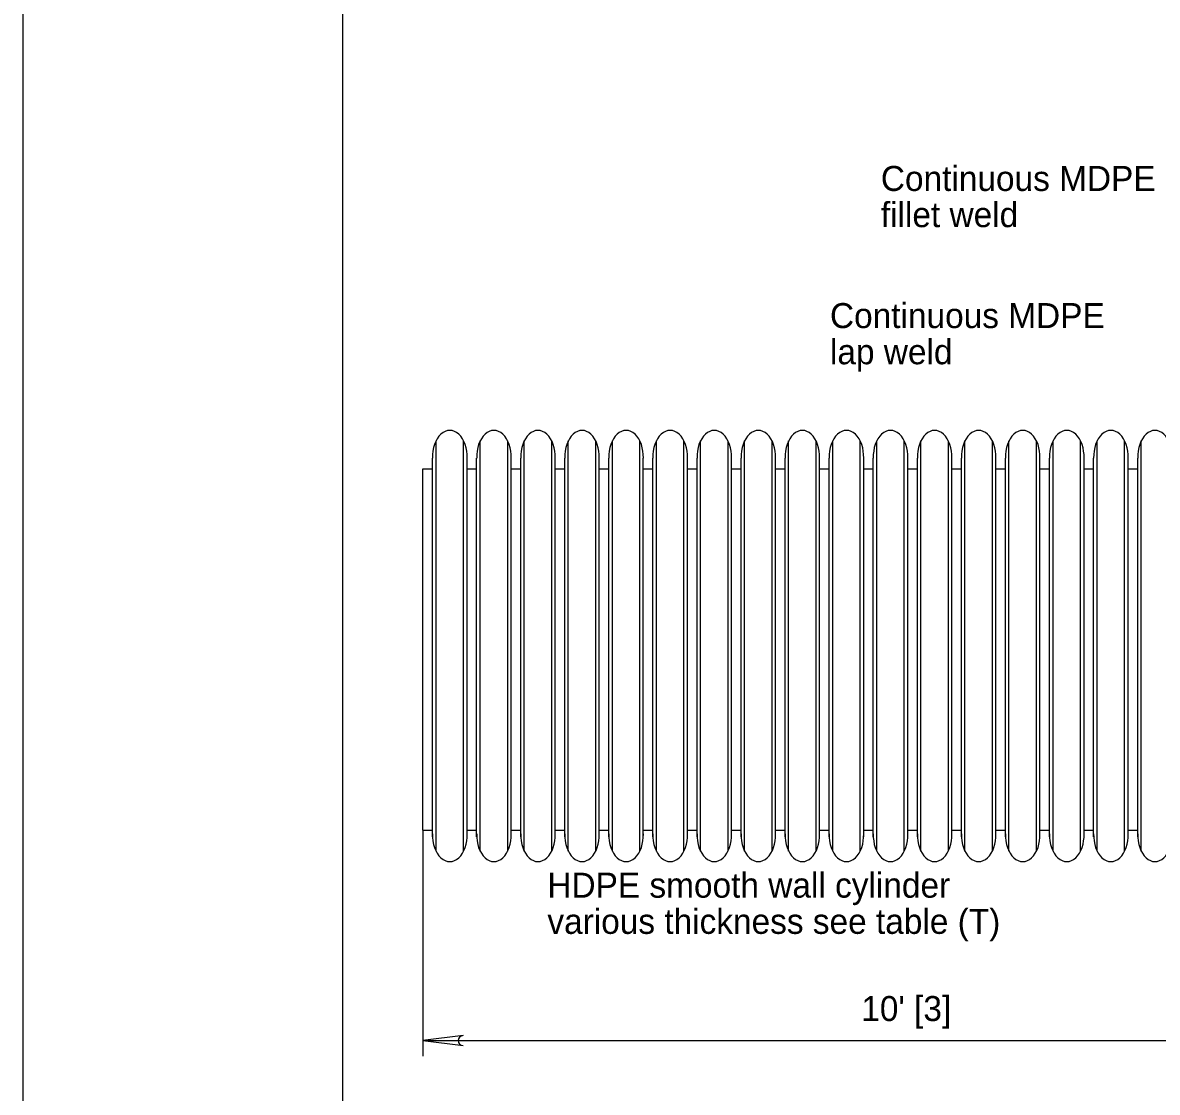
# Model space of a CAD drawing. Extents: x 1083.1 to 1117.1, y 675.4 to 741.4.
# Drawn here: x 1083.13 to 1090.21, y 684.37 to 691.05 of the extents above; entities that cross this region are included whole.
import ezdxf

# ---------------------------------------------------------------- set-up
doc = ezdxf.new("R2010")
doc.units = 0
doc.layers.add('Level 1', color=7, linetype='Continuous')
doc.layers.add('Level 44', color=7, linetype='Continuous')

msp = doc.modelspace()

# ---------------------------------------------------------------- linework, layer by layer
at = {"layer": 'Level 1'}
for p, q in [((1083.1264, 697.3541), (1083.1264, 675.3541)), ((1085.7082, 685.8738), (1085.7082, 688.4351)), ((1085.8803, 685.8738), (1085.8803, 688.4351)), ((1085.9834, 685.8738), (1085.9834, 688.4351)), ((1086.1556, 685.8738), (1086.1556, 688.4351)), ((1086.2587, 685.8738), (1086.2587, 688.4351)), ((1086.4308, 685.8738), (1086.4308, 688.4351)), ((1086.5339, 685.8738), (1086.5339, 688.4351)), ((1086.7061, 685.8738), (1086.7061, 688.4351)), ((1086.8092, 685.8738), (1086.8092, 688.4351)), ((1086.9813, 685.8738), (1086.9813, 688.4351)), ((1087.0844, 685.8738), (1087.0844, 688.4351)), ((1087.2566, 685.8738), (1087.2566, 688.4351)), ((1087.3597, 685.8738), (1087.3597, 688.4351)), ((1087.5318, 685.8738), (1087.5318, 688.4351)), ((1087.6349, 685.8738), (1087.6349, 688.4351)), ((1087.8071, 685.8738), (1087.8071, 688.4351)), ((1087.9102, 685.8738), (1087.9102, 688.4351)), ((1088.0823, 685.8738), (1088.0823, 688.4351)), ((1088.1854, 685.8738), (1088.1854, 688.4351)), ((1088.3576, 685.8738), (1088.3576, 688.4351)), ((1088.4607, 685.8738), (1088.4607, 688.4351)), ((1088.6328, 685.8738), (1088.6328, 688.4351)), ((1088.7359, 685.8738), (1088.7359, 688.4351)), ((1088.9081, 685.8738), (1088.9081, 688.4351)), ((1089.0112, 685.8738), (1089.0112, 688.4351)), ((1089.1833, 685.8738), (1089.1833, 688.4351)), ((1089.2864, 685.8738), (1089.2864, 688.4351)), ((1089.4586, 685.8738), (1089.4586, 688.4351)), ((1089.5617, 685.8738), (1089.5617, 688.4351)), ((1089.7338, 685.8738), (1089.7338, 688.4351)), ((1089.8369, 685.8738), (1089.8369, 688.4351)), ((1090.0091, 685.8738), (1090.0091, 688.4351)), ((1090.1122, 685.8738), (1090.1122, 688.4351)), ((1085.6865, 685.9635), (1085.6865, 688.3271)), ((1085.9018, 685.9633), (1085.9018, 688.3271)), ((1085.9617, 685.9635), (1085.9617, 688.3271)), ((1086.1771, 685.9633), (1086.1771, 688.3271)), ((1086.237, 685.9635), (1086.237, 688.3271)), ((1086.4523, 685.9633), (1086.4523, 688.3271)), ((1086.5122, 685.9635), (1086.5122, 688.3271)), ((1086.7276, 685.9633), (1086.7276, 688.3271)), ((1086.7875, 685.9635), (1086.7875, 688.3271)), ((1087.0028, 685.9633), (1087.0028, 688.3271)), ((1087.0628, 685.9635), (1087.0628, 688.3271)), ((1087.2781, 685.9633), (1087.2781, 688.3271)), ((1087.338, 685.9635), (1087.338, 688.3271)), ((1087.5533, 685.9633), (1087.5533, 688.3271)), ((1087.6132, 685.9635), (1087.6132, 688.3271)), ((1087.8286, 685.9633), (1087.8286, 688.3271)), ((1087.8885, 685.9635), (1087.8885, 688.3271)), ((1088.1038, 685.9633), (1088.1038, 688.3271)), ((1088.1637, 685.9635), (1088.1637, 688.3271)), ((1088.3791, 685.9633), (1088.3791, 688.3271)), ((1088.439, 685.9635), (1088.439, 688.3271)), ((1088.6543, 685.9633), (1088.6543, 688.3271)), ((1088.7142, 685.9635), (1088.7142, 688.3271)), ((1088.9296, 685.9633), (1088.9296, 688.3271)), ((1088.9895, 685.9635), (1088.9895, 688.3271)), ((1089.2048, 685.9633), (1089.2048, 688.3271)), ((1089.2648, 685.9635), (1089.2648, 688.3271)), ((1089.4801, 685.9633), (1089.4801, 688.3271)), ((1089.54, 685.9635), (1089.54, 688.3271)), ((1089.7553, 685.9633), (1089.7553, 688.3271)), ((1089.8152, 685.9635), (1089.8152, 688.3271)), ((1090.0306, 685.9633), (1090.0306, 688.3271)), ((1090.0905, 685.9635), (1090.0905, 688.3271)), ((1085.6266, 686.0051), (1085.6266, 688.2614)), ((1085.6266, 688.2614), (1085.6865, 688.2614)), ((1085.9018, 688.2614), (1085.9617, 688.2614)), ((1086.1771, 688.2614), (1086.237, 688.2614)), ((1086.4523, 688.2614), (1086.5122, 688.2614)), ((1086.7276, 688.2614), (1086.7875, 688.2614)), ((1087.0028, 688.2614), (1087.0628, 688.2614)), ((1087.2781, 688.2614), (1087.338, 688.2614)), ((1087.5533, 688.2614), (1087.6132, 688.2614)), ((1087.8286, 688.2614), (1087.8885, 688.2614)), ((1088.1038, 688.2614), (1088.1637, 688.2614)), ((1088.3791, 688.2614), (1088.439, 688.2614)), ((1088.6543, 688.2614), (1088.7142, 688.2614)), ((1088.9296, 688.2614), (1088.9895, 688.2614)), ((1089.2048, 688.2614), (1089.2648, 688.2614)), ((1089.4801, 688.2614), (1089.54, 688.2614)), ((1089.7553, 688.2614), (1089.8152, 688.2614)), ((1090.0306, 688.2614), (1090.0905, 688.2614)), ((1085.6266, 686.0051), (1085.6865, 686.0051)), ((1085.6266, 686.0051), (1085.6266, 684.5927)), ((1085.9018, 686.0051), (1085.9617, 686.0051)), ((1086.1771, 686.0051), (1086.237, 686.0051)), ((1086.4523, 686.0051), (1086.5122, 686.0051)), ((1086.7276, 686.0051), (1086.7875, 686.0051)), ((1087.0028, 686.0051), (1087.0628, 686.0051)), ((1087.2781, 686.0051), (1087.338, 686.0051)), ((1087.5533, 686.0051), (1087.6132, 686.0051)), ((1087.8286, 686.0051), (1087.8885, 686.0051)), ((1088.1038, 686.0051), (1088.1637, 686.0051)), ((1088.3791, 686.0051), (1088.439, 686.0051)), ((1088.6543, 686.0051), (1088.7142, 686.0051)), ((1088.9296, 686.0051), (1088.9895, 686.0051)), ((1089.2048, 686.0051), (1089.2648, 686.0051)), ((1089.4801, 686.0051), (1089.54, 686.0051)), ((1089.7553, 686.0051), (1089.8152, 686.0051)), ((1090.0306, 686.0051), (1090.0905, 686.0051)), ((1085.6266, 684.6905), (1092.023, 684.6905))]:
    msp.add_line(p, q, dxfattribs=at)
msp.add_lwpolyline([(1085.1264, 696.8541), (1116.6264, 696.8541), (1116.6264, 675.8541), (1085.1264, 675.8541)], close=True, dxfattribs=at)
for centre, major_axis, start_param, end_param in [((1085.7942, 688.3363), (0, -0.1643), 1.513563, 4.768623), ((1086.0695, 688.3363), (0, -0.1643), 1.513563, 4.768623), ((1086.3447, 688.3363), (0, -0.1643), 1.513563, 4.768623), ((1086.62, 688.3363), (0, -0.1643), 1.513563, 4.768623), ((1086.8952, 688.3363), (0, -0.1643), 1.513563, 4.768623), ((1087.1705, 688.3363), (0, -0.1643), 1.513563, 4.768623), ((1087.4457, 688.3363), (0, -0.1643), 1.513563, 4.768623), ((1087.721, 688.3363), (0, -0.1643), 1.513563, 4.768623), ((1087.9962, 688.3363), (0, -0.1643), 1.513563, 4.768623), ((1088.2715, 688.3363), (0, -0.1643), 1.513563, 4.768623), ((1088.5467, 688.3363), (0, -0.1643), 1.513563, 4.768623), ((1088.822, 688.3363), (0, -0.1643), 1.513563, 4.768623), ((1089.0972, 688.3363), (0, -0.1643), 1.513563, 4.768623), ((1089.3725, 688.3363), (0, -0.1643), 1.513563, 4.768623), ((1089.6477, 688.3363), (0, -0.1643), 1.513563, 4.768623), ((1089.923, 688.3363), (0, -0.1643), 1.513563, 4.768623), ((1090.1982, 688.3363), (0, -0.1643), 1.513563, 4.768623), ((1085.7942, 685.9727), (0, 0.1643), 1.514563, 4.769622), ((1086.0695, 685.9727), (0, 0.1643), 1.514563, 4.769622), ((1086.3447, 685.9727), (0, 0.1643), 1.514563, 4.769622), ((1086.62, 685.9727), (0, 0.1643), 1.514563, 4.769622), ((1086.8952, 685.9727), (0, 0.1643), 1.514563, 4.769622), ((1087.1705, 685.9727), (0, 0.1643), 1.514563, 4.769622), ((1087.4457, 685.9727), (0, 0.1643), 1.514563, 4.769622), ((1087.721, 685.9727), (0, 0.1643), 1.514563, 4.769622), ((1087.9962, 685.9727), (0, 0.1643), 1.514563, 4.769622), ((1088.2715, 685.9727), (0, 0.1643), 1.514563, 4.769622), ((1088.5467, 685.9727), (0, 0.1643), 1.514563, 4.769622), ((1088.822, 685.9727), (0, 0.1643), 1.514563, 4.769622), ((1089.0972, 685.9727), (0, 0.1643), 1.514563, 4.769622), ((1089.3725, 685.9727), (0, 0.1643), 1.514563, 4.769622), ((1089.6477, 685.9727), (0, 0.1643), 1.514563, 4.769622), ((1089.923, 685.9727), (0, 0.1643), 1.514563, 4.769622), ((1090.1982, 685.9727), (0, 0.1643), 1.514563, 4.769622)]:
    msp.add_ellipse(centre, major_axis=major_axis, ratio=0.6561, start_param=start_param, end_param=end_param, dxfattribs=at)
at = {"layer": 'Level 44'}
for p, q in [((1085.8766, 684.7217), (1085.6266, 684.6905)), ((1085.6266, 684.6905), (1085.8766, 684.6592))]:
    msp.add_line(p, q, dxfattribs=at)
msp.add_arc((1085.8766, 684.6905), 0.0312, 90, 270, dxfattribs=at)

# ---------------------------------------------------------------- texts
at = {"layer": 'Level 1'}
for s, p in [('Continuous MDPE', (1088.4863, 689.9957)), ('fillet weld', (1088.4863, 689.7697)), ('Continuous MDPE', (1088.1685, 689.1396)), ('lap weld', (1088.1685, 688.9136)), ('HDPE smooth wall cylinder', (1086.4035, 685.583)), ('various thickness see table (T)', (1086.4035, 685.357)), ("10' [3]", (1088.3641, 684.8128))]:
    msp.add_text(s, height=0.156, dxfattribs=at).set_placement(p)

doc.saveas('drawing.dxf')
